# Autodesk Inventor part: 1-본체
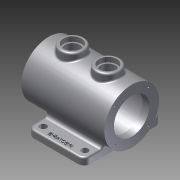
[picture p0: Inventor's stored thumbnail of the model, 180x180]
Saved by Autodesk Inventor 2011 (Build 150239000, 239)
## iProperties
Created: 2014-12
Part Number: 1-본체
Document SubType Name: Modeling
Designer: user
Density: 1 g/cm^3
Author: user
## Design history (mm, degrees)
sketch "스케치1"
  geometry: L1 (-47.5, 65)-(47.5, 65); L2 (47.5, 65)-(47.5, -65); L3 (47.5, -65)-(-47.5, -65); L4 (-47.5, -65)-(-47.5, 65); 3 further points
  constraints: 8 end point, 2 midpoint, 2 parallel, 1 horizontal, 1 horizontal alignment, 1 perpendicular, 1 vertical alignment
  dimensions: "d0" = 95 distance of L2.end L3.end; "d1" = 130 distance of L3.end L1.start
extrude "돌출1" new body sketch "스케치1" distance "d2" = 12; taper "d3" = 0 deg
node "작업 평면1"
sketch "스케치2"
  geometry: L1 (0, 130)-(0, 0) reference; C1 r 46 at (-50, 65); 2 further points
  constraints: 1 centre point, 1 horizontal alignment, 1 midpoint
  dimensions: "d5" = 50 distance from line of L1 C1.centre; "d6" = 92 diameter of C1
extrude "돌출2" join sketch "스케치2" distance "d7" = 140; taper "d8" = 0 deg
node "작업 평면2"
sketch "스케치3"
  geometry: L1 (62.5, 46)-(62.5, -46) reference; L2 (-77.5, -46)-(-77.5, 46) reference; L3 (-47.5, -25.923)-(-47.5, 25.923) reference; L4 (47.5, -25.923)-(-47.5, -25.923) reference; L5 (47.5, 25.923)-(47.5, -25.923) reference; L6 (-47.5, 25.923)-(47.5, 25.923) reference; L7 (-47.5, 25.923)-(47.5, 25.923) reference; L8 (47.5, 65)-(47.5, 25.923) reference; L9 (-47.5, 65)-(47.5, 65) reference; L10 (-47.5, 25.923)-(-47.5, 65) reference; L11 (47.5, -25.923)-(-47.5, -25.923) reference; L12 (-47.5, -65)-(-47.5, -25.923) reference; L13 (47.5, -65)-(-47.5, -65) reference; L14 (47.5, -25.923)-(47.5, -65) reference; C1 r 20 at (22.5, 0); C2 r 20 at (-37.5, 0); 1 further point
  constraints: 2 centre point, 2 horizontal alignment
  dimensions: "d10" = 40 diameter of C1; "d11" = 40 diameter of C2; "d12" = 40 distance from line of C1.centre L1; "d13" = 60 distance of C2.centre C1.centre
extrude "돌출3" join sketch "스케치3" distance "d14" = 30; taper "d15" = 0 deg
hole "Hole1" diameter "d18" = 25; stored, may be unused: countersink angle "d22" = 90 deg, drill point angle "d24" = 0 deg; dims "d16" = 10, "d17" = 10, "d19" = 6, "d20" = 30, "d21" = 8, "d23" = 30
hole "Hole2" diameter "d27" = 25; stored, may be unused: countersink angle "d31" = 90 deg, drill point angle "d33" = 0 deg; dims "d25" = 10, "d26" = 10, "d28" = 6, "d29" = 30, "d30" = 8, "d32" = 30
sketch "스케치4"
  geometry: C1 r 46 at (0, 0) reference; 1 further point
hole "Hole3" diameter "d36" = 60; stored, may be unused: countersink angle "d40" = 90 deg, drill point angle "d42" = 118 deg; dims "d34" = 10, "d35" = 10, "d37" = 6, "d38" = 30, "d39" = 8, "d41" = 30
node "작업 평면3"
sketch "스케치5"
  geometry: L1 (38, 65)-(50, 65) reference; L2 (50, 65)-(50, -65) reference; L3 (50, -65)-(38, -65) reference; L4 (38, -65)-(38, -25.923) reference; L5 (38, 25.923)-(38, 65) reference; C1 r 30 at (0, 0) reference; C2 r 37.5 at (0, 0); A1 r 46 centre (0, 0) between (38, 25.923) and (38, -25.923) reference; 1 further point
  constraints: 1 centre point, 1 coincident
  dimensions: "d43" = 75 diameter of C2
extrude "돌출4" cut sketch "스케치5" stored distance "d44" = 116; taper "d45" = 0 deg
sketch "스케치6" dims "d47" = 80
  geometry: L1 (0, 0)-(0, -56.477); L2 (0, 0)-(-69.697, -69.697); C1 r 30 at (0, 0) reference; 3 further points
  constraints: 4 end point, 1 coincident, 1 point on line, 1 vertical, 3 other
  dimensions: "d46" = 45 deg angle of L1 L2
hole "Hole4" sketch "스케치6" at (-28.284, -28.284) diameter "d48" = 3.242; stored, may be unused: countersink angle "d52" = 90 deg, drill point angle "d54" = 118 deg; dims "d49" = 8, "d50" = 30, "d51" = 8, "d53" = 10
fillet "모깎기1" dims "d58" = 10
fillet "모깎기2" dims "d95" = 5
fillet "모깎기3" dims "d96" = 3
fillet "모깎기4" dims "d97" = 3
fillet "모깎기5" dims "d98" = 3
sketch "스케치7"
  geometry: L1 (-47.5, 55)-(-47.5, 38.884) reference; L2 (37.5, 65)-(-37.5, 65) reference; C1 r 5.5 at (-35, 52.5); C2 r 5.5 at (35, 52.5); C3 r 5.5 at (35, -51.5); C4 r 5.5 at (-35, -51.5); 1 further point
  constraints: 4 centre point, 2 horizontal alignment, 2 vertical alignment
  dimensions: "d99" = 11 diameter of C1; "d100" = 11 diameter of C2; "d101" = 11 diameter of C3; "d102" = 11 diameter of C4; "d103" = 70 distance of C2.centre C1.centre; "d104" = 12.5 distance from line of C1.centre L1; "d105" = 104 distance of C4.centre C1.centre; "d106" = 12.5 distance from line of C1.centre L2
extrude "돌출5" cut sketch "스케치7" distance "d107" = 116; taper "d108" = 0 deg
sketch "스케치8"
  geometry: L1 (-20.739, -53.998)-(20.739, -53.998); L2 (20.739, -53.998)-(20.739, -60.002); L3 (20.739, -60.002)-(-20.739, -60.002); L4 (-20.739, -60.002)-(-20.739, -53.998); L5 (37.5, 65)-(-37.5, 65) reference; L6 (-37.5, -65)-(37.5, -65) reference; 4 further points
  constraints: 3 midpoint, 1 vertical alignment, 2 other
  dimensions: "d109" = 8 distance from line of point (-20.739, -57) L6
feature "엠보싱1" sketch "스케치8" dims "d0" = 95, "d1" = 130, "d110" = 1, "d111" = 0
node "솔리드1"
pattern_circular "원형 패턴1" dims angle "d56" = 360 deg
mirror "대칭1"
node "투영된 루프1"
node "투영된 루프2"
node "투영된 루프3"
node "절단 모서리 투영1"
other parameters: "d4" = 15, "d9" = -106
